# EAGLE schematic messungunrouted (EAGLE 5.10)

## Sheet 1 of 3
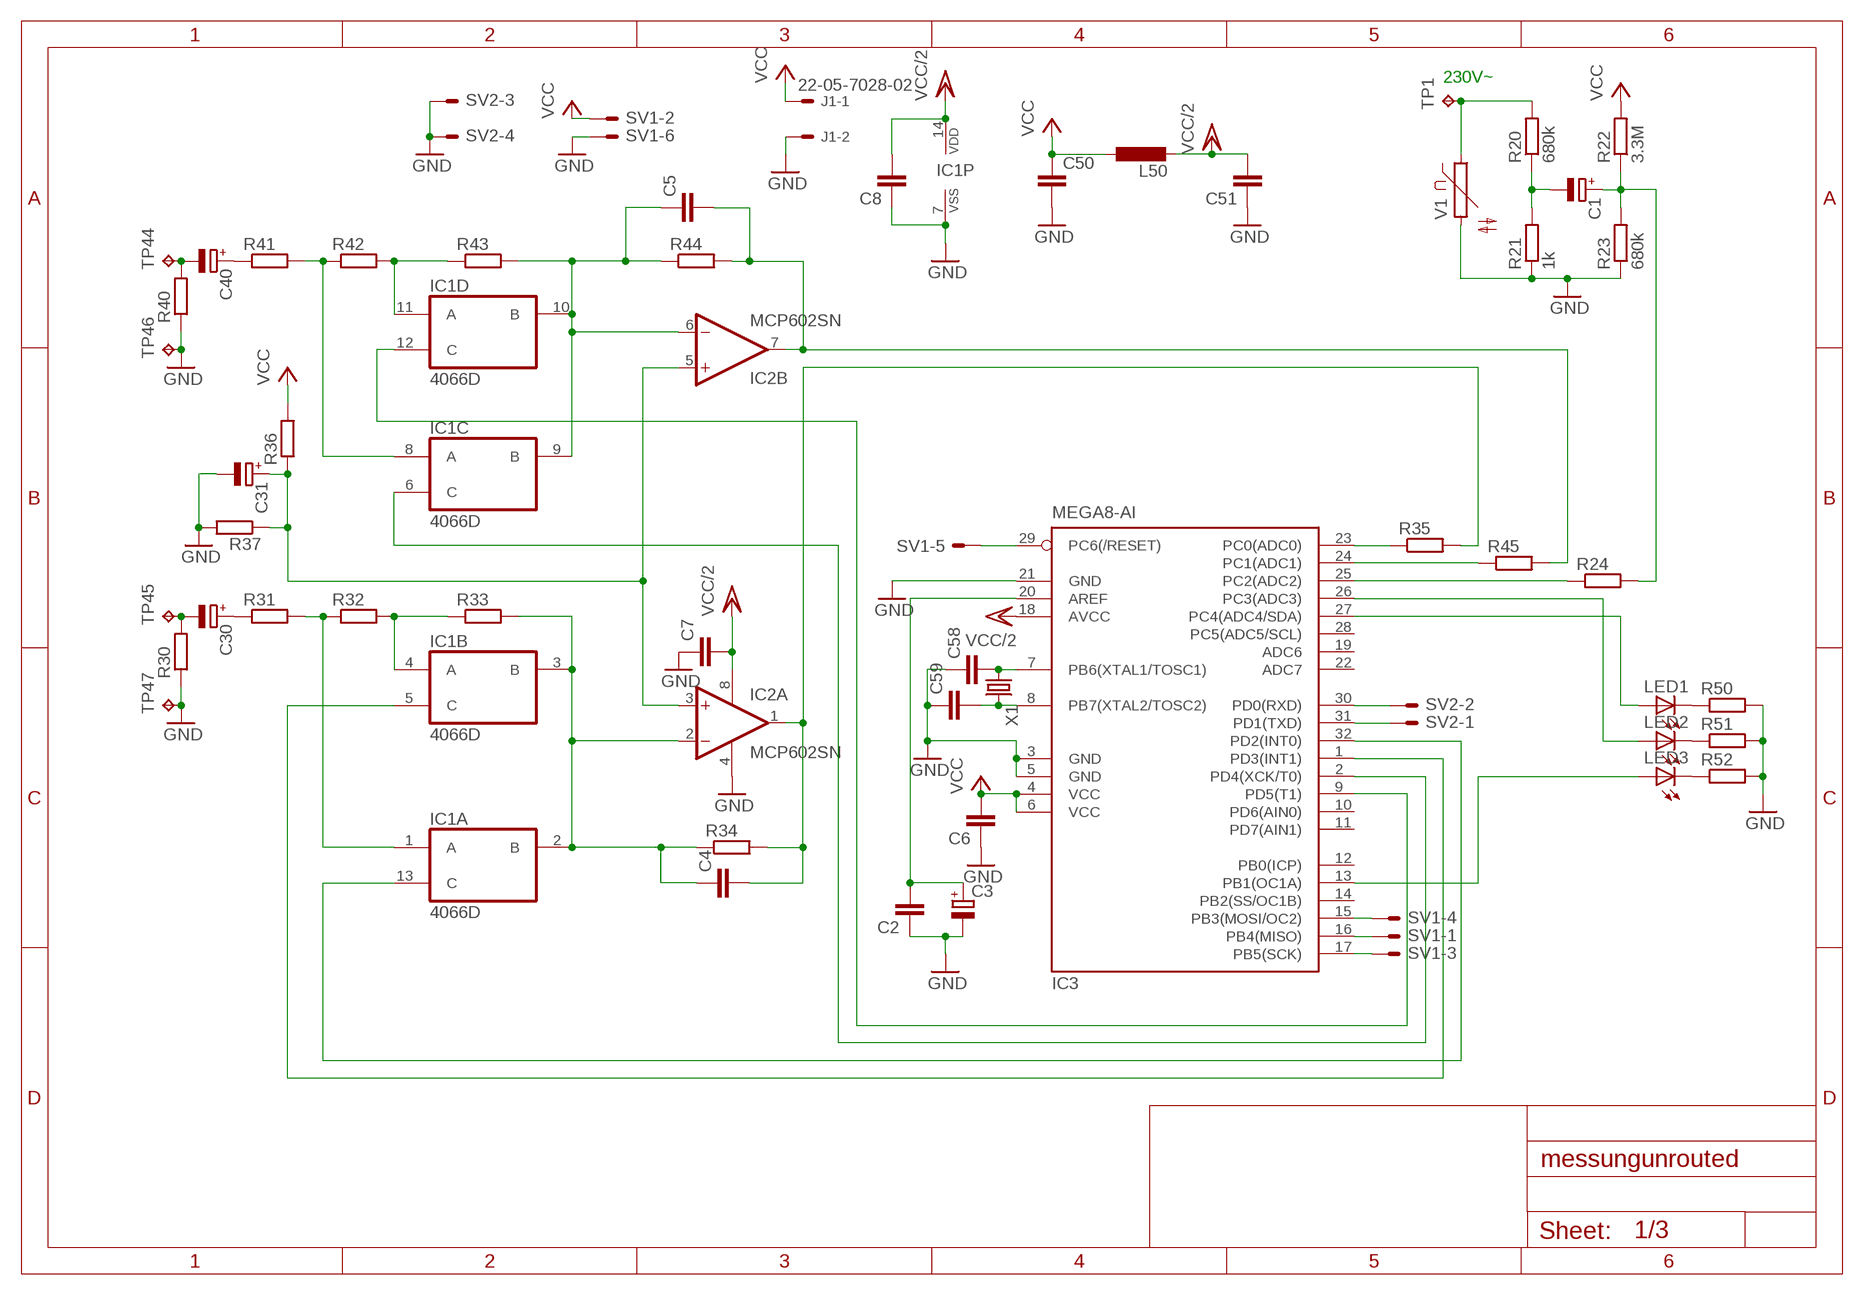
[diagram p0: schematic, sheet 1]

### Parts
C1  CPOL-EUE2-5  [E2-5]
C2  C-EU025-025X050  [C025-025X050]
C3  CPOL-EUE2-5  [E2-5]
C4  C-EU025-025X050  [C025-025X050]
C5  C-EU025-025X050  [C025-025X050]
C6  C-EU025-025X050  [C025-025X050]
C7  C-EU025-025X050  [C025-025X050]
C8  C-EU025-025X050  [C025-025X050]
C30  CPOL-EUE2-5  [E2-5]
C31  CPOL-EUE2-5  [E2-5]
C40  CPOL-EUE2-5  [E2-5]
C50  C-EU025-025X050  [C025-025X050]
C51  C-EU025-025X050  [C025-025X050]
C58  C-EU025-025X050  [C025-025X050]
C59  C-EU025-025X050  [C025-025X050]
IC1  4066D  [SO14]
IC2  MCP602SN  [SO08]
IC3  MEGA8-AI  [TQFP32-08]
J1  22-05-7028-02  [7395-02]
L50  L-EU0207/15  [0207/15]
LED1  LEDCHIPLED_1206  [CHIPLED_1206]
LED2  LEDCHIPLED_1206  [CHIPLED_1206]
LED3  LEDCHIPLED_1206  [CHIPLED_1206]
R20  680k  R-EU_0207/12  [0207/12]
R21  1k  R-EU_0207/12  [0207/12]
R22  3.3M  R-EU_0207/12  [0207/12]
R23  680k  R-EU_0207/12  [0207/12]
R24  R-EU_0207/12  [0207/12]
R30  R-EU_0207/12  [0207/12]
R31  R-EU_0207/12  [0207/12]
R32  R-EU_0207/12  [0207/12]
R33  R-EU_0207/12  [0207/12]
R34  R-EU_0207/12  [0207/12]
R35  R-EU_0207/12  [0207/12]
R36  R-EU_0207/12  [0207/12]
R37  R-EU_0207/12  [0207/12]
R40  R-EU_0207/12  [0207/12]
R41  R-EU_0207/12  [0207/12]
R42  R-EU_0207/12  [0207/12]
R43  R-EU_0207/12  [0207/12]
R44  R-EU_0207/12  [0207/12]
R45  R-EU_0207/12  [0207/12]
R50  R-EU_M1206  [M1206]
R51  R-EU_M1206  [M1206]
R52  R-EU_M1206  [M1206]
SV1  ML6E  [ML6]
SV2  ML6E  [ML6]
TP1  TPPAD1-20Y  [P1-20Y]
TP44  TPPAD1-17  [P1-17]
TP45  TPPAD1-17  [P1-17]
TP46  TPPAD1-17  [P1-17]
TP47  TPPAD1-17  [P1-17]
V1  P593  [P593]
X1  CRYSTALHC49S  [HC49/S]

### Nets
GND: C2.1 C3.- C6.1 C7.1 C8.1 C31.- C50.2 C51.1 C58.1 C59.1 IC1.7(P:VSS) IC2.4(P:V-) IC3.3(GND) IC3.5(GND) IC3.21(GND) J1.2 R21.1 R23.1 R30.1 R37.2 R40.1 R50.2 R51.2 R52.2 SV1.6 SV2.3 SV2.4 TP46.TP TP47.TP V1.2 ; also sheet 2,3
N$1: LED1.C R50.1
N$2: LED2.C R51.1
N$3: LED3.C R52.1
N$4: C1.+ R22.1 R23.2 R24.2
N$5: C1.- R20.1 R21.2
N$6: C4.1 IC1.2(A:B) IC1.3(B:B) IC2.2(A:-IN) R33.2 R34.1
N$7: R20.2 TP1.TP V1.1
N$8: IC1.4(B:A) R32.2 R33.1
N$9: IC1.1(A:A) R31.2 R32.1
N$10: C30.+ R31.1
N$12: C5.1 IC1.9(C:B) IC1.10(D:B) IC2.6(B:-IN) R43.2 R44.1
N$13: IC1.11(D:A) R42.2 R43.1
N$14: IC1.8(C:A) R41.2 R42.1
N$15: C40.+ R41.1
N$16: C40.- R40.2 TP44.TP
N$17: C5.2 IC2.7(B:OUT) R44.2 R45.2
N$18: C4.2 IC2.1(A:OUT) R34.2 R35.2
N$19: C31.+ IC2.3(A:+IN) IC2.5(B:+IN) R36.1 R37.1
N$20: IC3.29(PC6(/RESET)) SV1.5
N$21: IC3.15(PB3(MOSI/OC2)) SV1.4
N$22: IC3.16(PB4(MISO)) SV1.1
N$23: IC3.17(PB5(SCK)) SV1.3
N$24: IC3.13(PB1(OC1A)) LED3.A
N$25: IC3.26(PC3(ADC3)) LED2.A
N$26: IC3.27(PC4(ADC4/SDA)) LED1.A
N$27: C30.- R30.2 TP45.TP
N$29: IC3.25(PC2(ADC2)) R24.1
N$30: IC3.24(PC1(ADC1)) R45.1
N$31: IC3.23(PC0(ADC0)) R35.1
N$32: IC1.6(C:C) IC3.2(PD4(XCK/T0))
N$33: IC1.13(A:C) IC3.32(PD2(INT0))
N$34: IC1.5(B:C) IC3.1(PD3(INT1))
N$35: IC1.12(D:C) IC3.9(PD5(T1))
N$36: C59.2 IC3.8(PB7(XTAL2/TOSC2)) X1.2
N$37: C58.2 IC3.7(PB6(XTAL1/TOSC1)) X1.1
N$38: IC3.30(PD0(RXD)) SV2.2
N$39: C2.2 C3.+ IC3.20(AREF)
N$40: IC3.31(PD1(TXD)) SV2.1
VCC: C6.2 C50.1 IC3.4(VCC) IC3.6(VCC) J1.1 L50.1 R22.2 R36.2 SV1.2 ; also sheet 2,3
VCC/2: C7.2 C8.2 C51.2 IC1.14(P:VDD) IC2.8(P:V+) IC3.18(AVCC) L50.2 ; also sheet 2,3
Unconnected: IC3.10(PD6(AIN0)) IC3.11(PD7(AIN1)) IC3.12(PB0(ICP)) IC3.14(PB2(SS/OC1B)) IC3.19(ADC6) IC3.22(ADC7) IC3.28(PC5(ADC5/SCL)) SV2.5 SV2.6

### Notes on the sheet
- 230V~

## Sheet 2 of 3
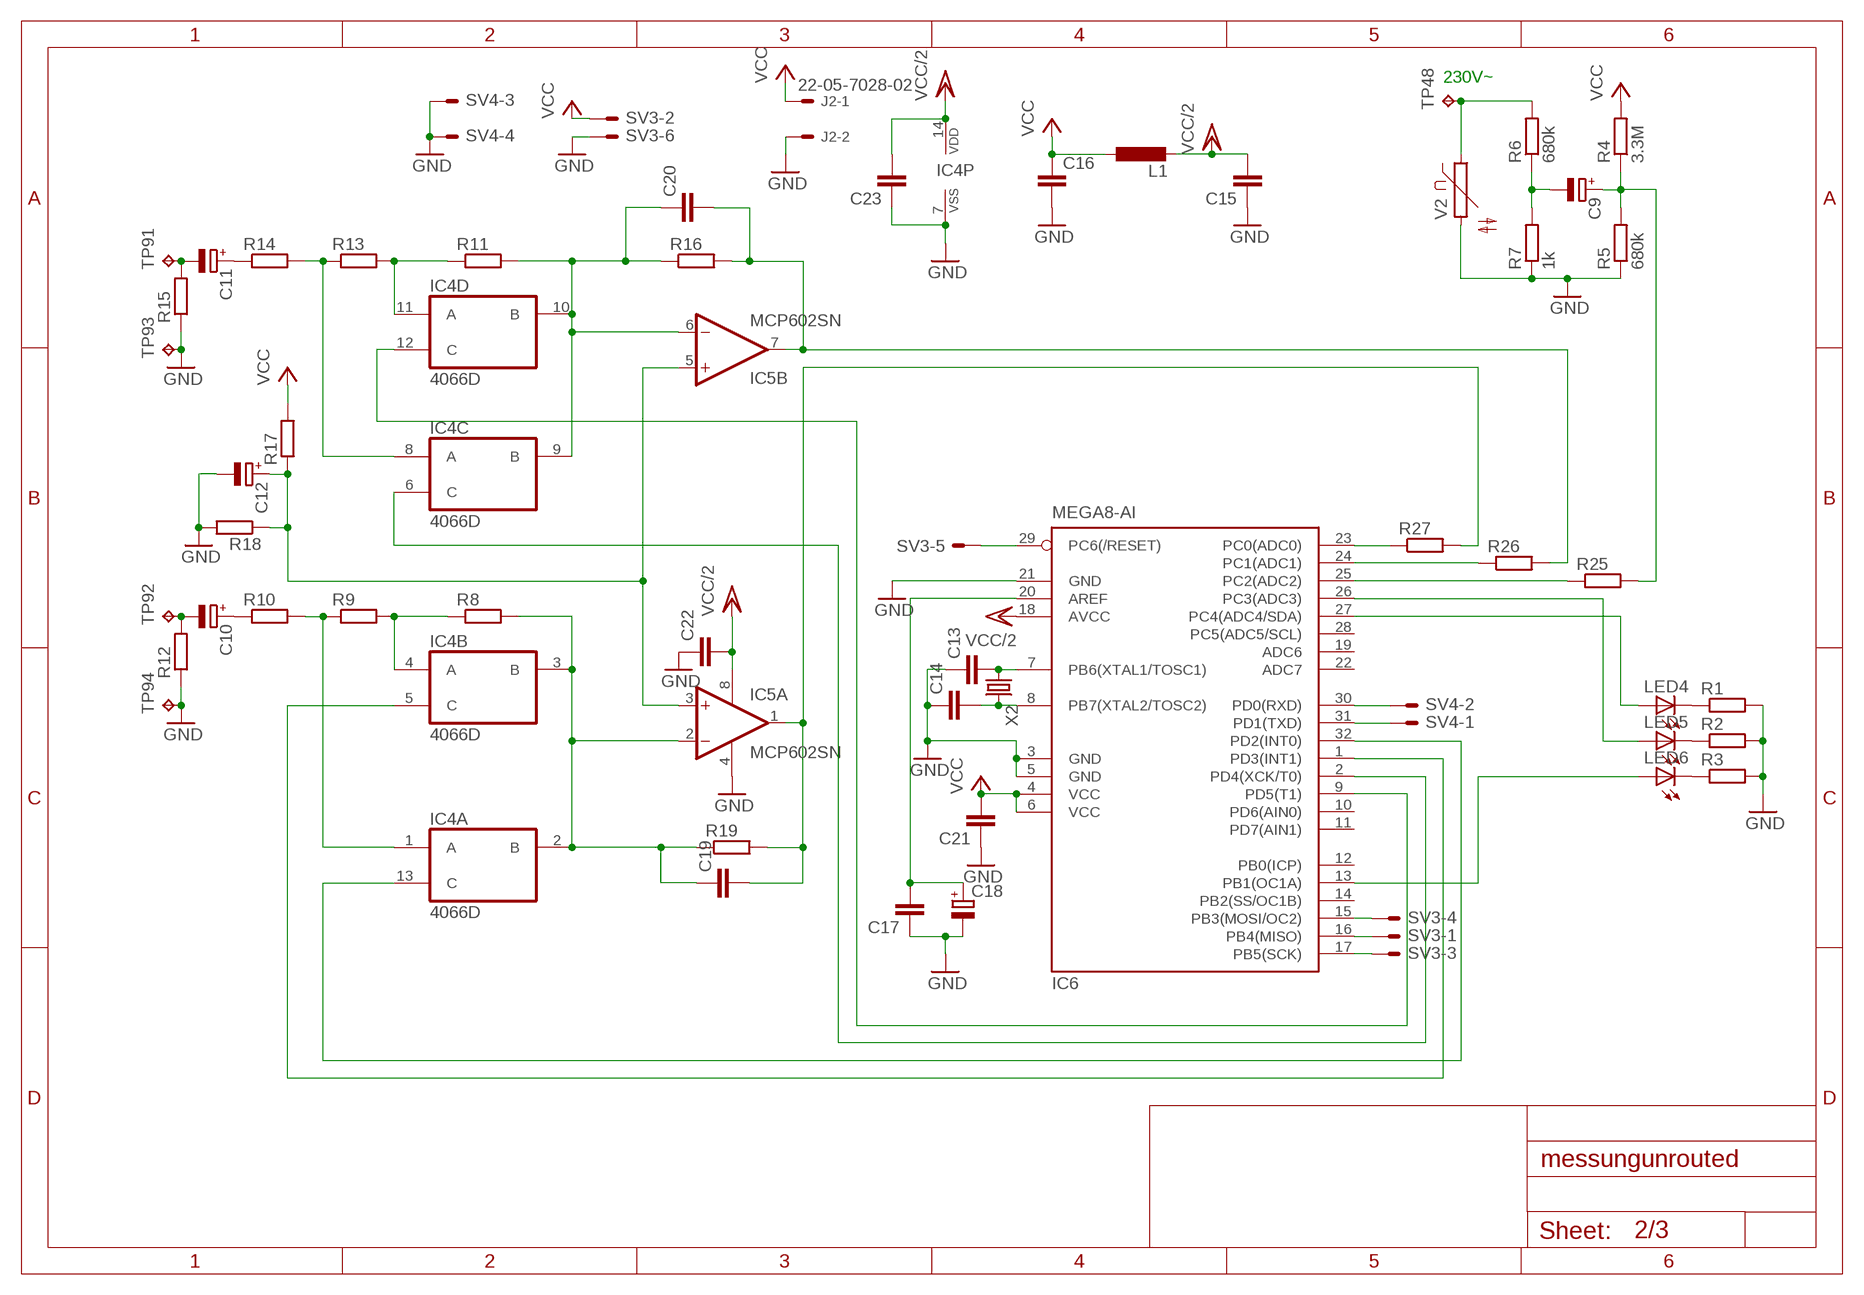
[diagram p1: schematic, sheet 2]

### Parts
C9  CPOL-EUE2-5  [E2-5]
C10  CPOL-EUE2-5  [E2-5]
C11  CPOL-EUE2-5  [E2-5]
C12  CPOL-EUE2-5  [E2-5]
C13  C-EU025-025X050  [C025-025X050]
C14  C-EU025-025X050  [C025-025X050]
C15  C-EU025-025X050  [C025-025X050]
C16  C-EU025-025X050  [C025-025X050]
C17  C-EU025-025X050  [C025-025X050]
C18  CPOL-EUE2-5  [E2-5]
C19  C-EU025-025X050  [C025-025X050]
C20  C-EU025-025X050  [C025-025X050]
C21  C-EU025-025X050  [C025-025X050]
C22  C-EU025-025X050  [C025-025X050]
C23  C-EU025-025X050  [C025-025X050]
IC4  4066D  [SO14]
IC5  MCP602SN  [SO08]
IC6  MEGA8-AI  [TQFP32-08]
J2  22-05-7028-02  [7395-02]
L1  L-EU0207/15  [0207/15]
LED4  LEDCHIPLED_1206  [CHIPLED_1206]
LED5  LEDCHIPLED_1206  [CHIPLED_1206]
LED6  LEDCHIPLED_1206  [CHIPLED_1206]
R1  R-EU_M1206  [M1206]
R2  R-EU_M1206  [M1206]
R3  R-EU_M1206  [M1206]
R4  3.3M  R-EU_0207/12  [0207/12]
R5  680k  R-EU_0207/12  [0207/12]
R6  680k  R-EU_0207/12  [0207/12]
R7  1k  R-EU_0207/12  [0207/12]
R8  R-EU_0207/12  [0207/12]
R9  R-EU_0207/12  [0207/12]
R10  R-EU_0207/12  [0207/12]
R11  R-EU_0207/12  [0207/12]
R12  R-EU_0207/12  [0207/12]
R13  R-EU_0207/12  [0207/12]
R14  R-EU_0207/12  [0207/12]
R15  R-EU_0207/12  [0207/12]
R16  R-EU_0207/12  [0207/12]
R17  R-EU_0207/12  [0207/12]
R18  R-EU_0207/12  [0207/12]
R19  R-EU_0207/12  [0207/12]
R25  R-EU_0207/12  [0207/12]
R26  R-EU_0207/12  [0207/12]
R27  R-EU_0207/12  [0207/12]
SV3  ML6E  [ML6]
SV4  ML6E  [ML6]
TP48  TPPAD1-20Y  [P1-20Y]
TP91  TPPAD1-17  [P1-17]
TP92  TPPAD1-17  [P1-17]
TP93  TPPAD1-17  [P1-17]
TP94  TPPAD1-17  [P1-17]
V2  P593  [P593]
X2  CRYSTALHC49S  [HC49/S]

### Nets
GND: C12.- C13.1 C14.1 C15.1 C16.2 C17.1 C18.- C21.1 C22.1 C23.1 IC4.7(P:VSS) IC5.4(P:V-) IC6.3(GND) IC6.5(GND) IC6.21(GND) J2.2 R1.2 R2.2 R3.2 R5.1 R7.1 R12.1 R15.1 R18.2 SV3.6 SV4.3 SV4.4 TP93.TP TP94.TP V2.2 ; also sheet 1,3
N$11: LED4.C R1.1
N$28: LED5.C R2.1
N$41: LED6.C R3.1
N$42: C9.+ R4.1 R5.2 R25.2
N$43: C9.- R6.1 R7.2
N$44: R6.2 TP48.TP V2.1
N$45: C19.1 IC4.2(A:B) IC4.3(B:B) IC5.2(A:-IN) R8.2 R19.1
N$46: IC4.4(B:A) R8.1 R9.2
N$47: IC4.1(A:A) R9.1 R10.2
N$48: C10.+ R10.1
N$49: C20.1 IC4.9(C:B) IC4.10(D:B) IC5.6(B:-IN) R11.2 R16.1
N$50: IC4.11(D:A) R11.1 R13.2
N$51: IC4.8(C:A) R13.1 R14.2
N$52: C11.+ R14.1
N$53: C11.- R15.2 TP91.TP
N$54: C20.2 IC5.7(B:OUT) R16.2 R26.2
N$55: C12.+ IC5.3(A:+IN) IC5.5(B:+IN) R17.1 R18.1
N$56: C19.2 IC5.1(A:OUT) R19.2 R27.2
N$57: IC6.29(PC6(/RESET)) SV3.5
N$58: IC6.15(PB3(MOSI/OC2)) SV3.4
N$59: IC6.16(PB4(MISO)) SV3.1
N$60: IC6.17(PB5(SCK)) SV3.3
N$61: IC6.13(PB1(OC1A)) LED6.A
N$62: IC6.26(PC3(ADC3)) LED5.A
N$63: IC6.27(PC4(ADC4/SDA)) LED4.A
N$64: IC6.25(PC2(ADC2)) R25.1
N$65: IC6.24(PC1(ADC1)) R26.1
N$66: IC6.23(PC0(ADC0)) R27.1
N$67: IC4.13(A:C) IC6.32(PD2(INT0))
N$68: IC4.5(B:C) IC6.1(PD3(INT1))
N$69: IC4.6(C:C) IC6.2(PD4(XCK/T0))
N$70: IC4.12(D:C) IC6.9(PD5(T1))
N$71: C14.2 IC6.8(PB7(XTAL2/TOSC2)) X2.2
N$72: C13.2 IC6.7(PB6(XTAL1/TOSC1)) X2.1
N$73: C17.2 C18.+ IC6.20(AREF)
N$74: IC6.30(PD0(RXD)) SV4.2
N$75: IC6.31(PD1(TXD)) SV4.1
N$76: C10.- R12.2 TP92.TP
VCC: C16.1 C21.2 IC6.4(VCC) IC6.6(VCC) J2.1 L1.1 R4.2 R17.2 SV3.2 ; also sheet 1,3
VCC/2: C15.2 C22.2 C23.2 IC4.14(P:VDD) IC5.8(P:V+) IC6.18(AVCC) L1.2 ; also sheet 1,3
Unconnected: IC6.10(PD6(AIN0)) IC6.11(PD7(AIN1)) IC6.12(PB0(ICP)) IC6.14(PB2(SS/OC1B)) IC6.19(ADC6) IC6.22(ADC7) IC6.28(PC5(ADC5/SCL)) SV4.5 SV4.6

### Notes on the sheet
- 230V~

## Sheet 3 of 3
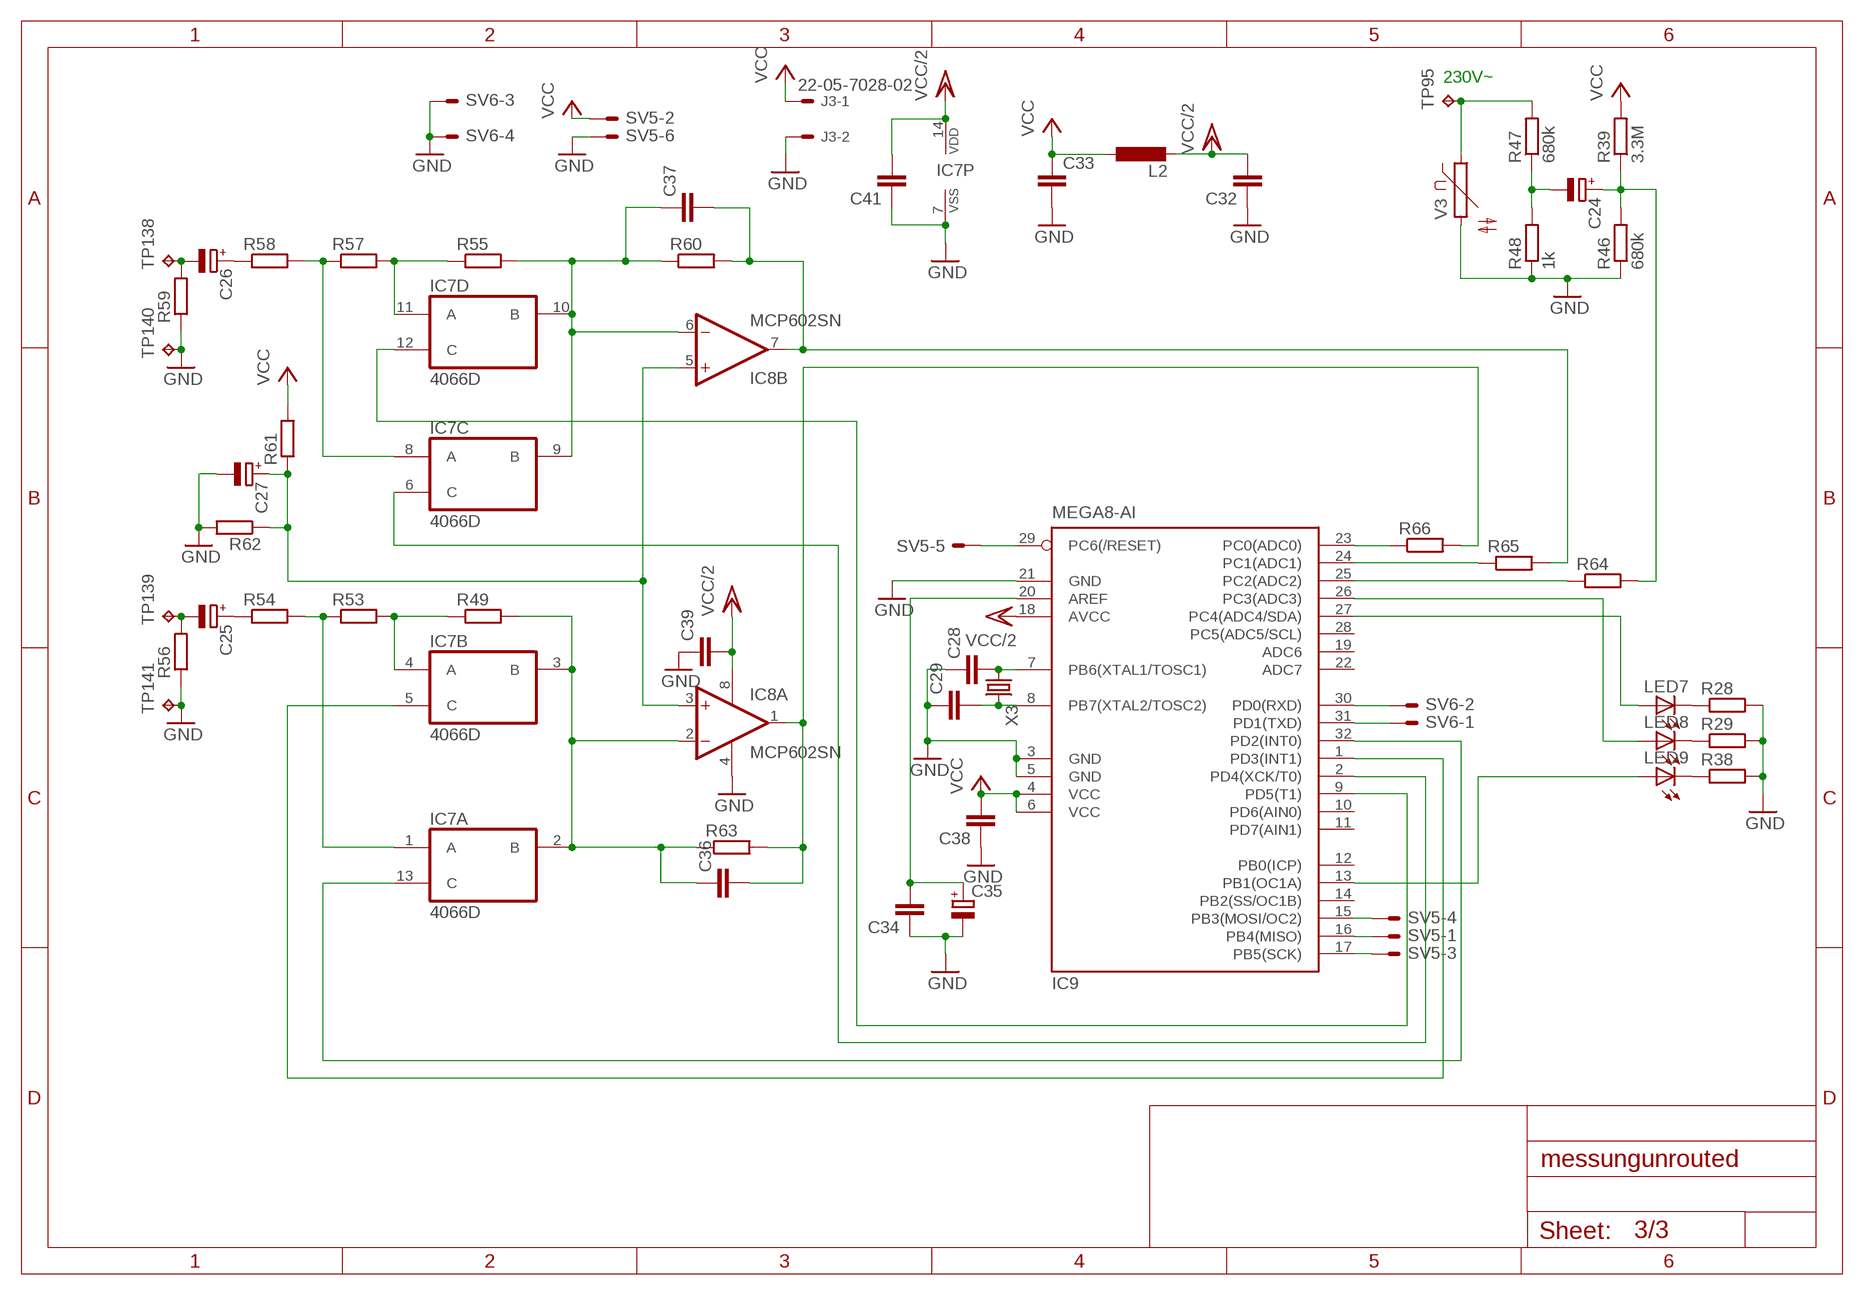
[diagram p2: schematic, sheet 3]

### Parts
C24  CPOL-EUE2-5  [E2-5]
C25  CPOL-EUE2-5  [E2-5]
C26  CPOL-EUE2-5  [E2-5]
C27  CPOL-EUE2-5  [E2-5]
C28  C-EU025-025X050  [C025-025X050]
C29  C-EU025-025X050  [C025-025X050]
C32  C-EU025-025X050  [C025-025X050]
C33  C-EU025-025X050  [C025-025X050]
C34  C-EU025-025X050  [C025-025X050]
C35  CPOL-EUE2-5  [E2-5]
C36  C-EU025-025X050  [C025-025X050]
C37  C-EU025-025X050  [C025-025X050]
C38  C-EU025-025X050  [C025-025X050]
C39  C-EU025-025X050  [C025-025X050]
C41  C-EU025-025X050  [C025-025X050]
IC7  4066D  [SO14]
IC8  MCP602SN  [SO08]
IC9  MEGA8-AI  [TQFP32-08]
J3  22-05-7028-02  [7395-02]
L2  L-EU0207/15  [0207/15]
LED7  LEDCHIPLED_1206  [CHIPLED_1206]
LED8  LEDCHIPLED_1206  [CHIPLED_1206]
LED9  LEDCHIPLED_1206  [CHIPLED_1206]
R28  R-EU_M1206  [M1206]
R29  R-EU_M1206  [M1206]
R38  R-EU_M1206  [M1206]
R39  3.3M  R-EU_0207/12  [0207/12]
R46  680k  R-EU_0207/12  [0207/12]
R47  680k  R-EU_0207/12  [0207/12]
R48  1k  R-EU_0207/12  [0207/12]
R49  R-EU_0207/12  [0207/12]
R53  R-EU_0207/12  [0207/12]
R54  R-EU_0207/12  [0207/12]
R55  R-EU_0207/12  [0207/12]
R56  R-EU_0207/12  [0207/12]
R57  R-EU_0207/12  [0207/12]
R58  R-EU_0207/12  [0207/12]
R59  R-EU_0207/12  [0207/12]
R60  R-EU_0207/12  [0207/12]
R61  R-EU_0207/12  [0207/12]
R62  R-EU_0207/12  [0207/12]
R63  R-EU_0207/12  [0207/12]
R64  R-EU_0207/12  [0207/12]
R65  R-EU_0207/12  [0207/12]
R66  R-EU_0207/12  [0207/12]
SV5  ML6E  [ML6]
SV6  ML6E  [ML6]
TP95  TPPAD1-20Y  [P1-20Y]
TP138  TPPAD1-17  [P1-17]
TP139  TPPAD1-17  [P1-17]
TP140  TPPAD1-17  [P1-17]
TP141  TPPAD1-17  [P1-17]
V3  P593  [P593]
X3  CRYSTALHC49S  [HC49/S]

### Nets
GND: C27.- C28.1 C29.1 C32.1 C33.2 C34.1 C35.- C38.1 C39.1 C41.1 IC7.7(P:VSS) IC8.4(P:V-) IC9.3(GND) IC9.5(GND) IC9.21(GND) J3.2 R28.2 R29.2 R38.2 R46.1 R48.1 R56.1 R59.1 R62.2 SV5.6 SV6.3 SV6.4 TP140.TP TP141.TP V3.2 ; also sheet 1,2
N$77: LED7.C R28.1
N$78: LED8.C R29.1
N$79: LED9.C R38.1
N$80: C24.+ R39.1 R46.2 R64.2
N$81: C24.- R47.1 R48.2
N$82: R47.2 TP95.TP V3.1
N$83: C36.1 IC7.2(A:B) IC7.3(B:B) IC8.2(A:-IN) R49.2 R63.1
N$84: IC7.4(B:A) R49.1 R53.2
N$85: IC7.1(A:A) R53.1 R54.2
N$86: C25.+ R54.1
N$87: C37.1 IC7.9(C:B) IC7.10(D:B) IC8.6(B:-IN) R55.2 R60.1
N$88: IC7.11(D:A) R55.1 R57.2
N$89: IC7.8(C:A) R57.1 R58.2
N$90: C26.+ R58.1
N$91: C26.- R59.2 TP138.TP
N$92: C37.2 IC8.7(B:OUT) R60.2 R65.2
N$93: C27.+ IC8.3(A:+IN) IC8.5(B:+IN) R61.1 R62.1
N$94: C36.2 IC8.1(A:OUT) R63.2 R66.2
N$95: IC9.29(PC6(/RESET)) SV5.5
N$96: IC9.15(PB3(MOSI/OC2)) SV5.4
N$97: IC9.16(PB4(MISO)) SV5.1
N$98: IC9.17(PB5(SCK)) SV5.3
N$99: IC9.13(PB1(OC1A)) LED9.A
N$100: IC9.26(PC3(ADC3)) LED8.A
N$101: IC9.27(PC4(ADC4/SDA)) LED7.A
N$102: IC9.25(PC2(ADC2)) R64.1
N$103: IC9.24(PC1(ADC1)) R65.1
N$104: IC9.23(PC0(ADC0)) R66.1
N$105: IC7.13(A:C) IC9.32(PD2(INT0))
N$106: IC7.5(B:C) IC9.1(PD3(INT1))
N$107: IC7.6(C:C) IC9.2(PD4(XCK/T0))
N$108: IC7.12(D:C) IC9.9(PD5(T1))
N$109: C29.2 IC9.8(PB7(XTAL2/TOSC2)) X3.2
N$110: C28.2 IC9.7(PB6(XTAL1/TOSC1)) X3.1
N$111: C34.2 C35.+ IC9.20(AREF)
N$112: IC9.30(PD0(RXD)) SV6.2
N$113: IC9.31(PD1(TXD)) SV6.1
N$114: C25.- R56.2 TP139.TP
VCC: C33.1 C38.2 IC9.4(VCC) IC9.6(VCC) J3.1 L2.1 R39.2 R61.2 SV5.2 ; also sheet 1,2
VCC/2: C32.2 C39.2 C41.2 IC7.14(P:VDD) IC8.8(P:V+) IC9.18(AVCC) L2.2 ; also sheet 1,2
Unconnected: IC9.10(PD6(AIN0)) IC9.11(PD7(AIN1)) IC9.12(PB0(ICP)) IC9.14(PB2(SS/OC1B)) IC9.19(ADC6) IC9.22(ADC7) IC9.28(PC5(ADC5/SCL)) SV6.5 SV6.6

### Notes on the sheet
- 230V~

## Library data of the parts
C1 C3 C9-C12 C18 C24-C27 C30 C31 C35 C40 = rcl:CPOL-EU: POLARIZED CAPACITOR, European symbol
C2 C4-C8 C13-C17 C19-C23 C28 C29 C32-C34 C36-C39 C41 C50 C51 C58 C59 = rcl:C-EU: CAPACITOR, European symbol
IC1 IC4 IC7 = 40xx:4066: Quad bilateral ANALOG SWITCH
IC2 IC5 IC8 = linear:MCP602: Single Op Amp 2.7V to 6.0V Single Supply CMOS Source: http://ww1.microchip.com/downloads/en/DeviceDoc/21314g.pdf
IC3 IC6 IC9 = atmel:MEGA8: MICROCONTROLLER 8 Kbytes FLASH, 1 kbytes SRAM, 512 bytes EEPROM, USART, 6-channel 10 bit ADC, 2-channel 8 bit ADC Pin compatible with Atmega48, ATMega88, ATMega168 Source: avr.lbr
J1-J3 = con-molex:22-?-02: CONNECTOR
L1 L2 L50 = rcl:L-EU: INDUCTOR, European symbol
LED1-LED9 = led:LED: LED
R1-R66 = rcl:R-EU_: RESISTOR, European symbol
SV1-SV6 = con-harting-ml:ML6?E: HARTING
TP1 TP44-TP48 TP91-TP95 TP138-TP141 = testpad:TP: Test pad
V1-V3 = varistor:P593: VARISTOR
X1-X3 = crystal:CRYSTAL: CRYSTAL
